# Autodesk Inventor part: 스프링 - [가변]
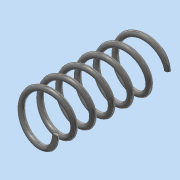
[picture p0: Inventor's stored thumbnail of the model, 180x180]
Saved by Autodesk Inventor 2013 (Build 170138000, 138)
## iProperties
Created: 2016-04
Part Number: 스프링 - [가변]
Material: 강철, 탄소
Document SubType Name: Modeling
Designer: dgall
Density: 7.87 g/cm^3
Mass: 7.38132 g
Surface Area: 18.9918 cm^2
Volume: 0.937905 cm^3
Author: dgall
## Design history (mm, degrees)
sketch "스케치1"
  geometry: L1 (0, 0)-(0, 42); L2 (0, 0)-(8, 0); L3 (0, 42)-(14.42, 42); C1 r 1 at (8, 0)
  constraints: 6 end point, 1 centre point, 1 coincident, 1 parallel, 1 perpendicular, 1 vertical
  dimensions: "d0" = 42 distance of L1.start L1.end (derived); "d1" = 16 diameter of L2.end L1; "d2" = 2 diameter of C1
feature "코일1" pitch "d3" = 10; turns "d5" = 6; dims "d4" = 42 (= d0), "d6" = 0, angle "d7" = 90 deg, angle "d8" = 90 deg, "d9" = 0, "d10" = 0
feature "분할1"
node "작업 평면1"
feature "분할2"
node "솔리드1"
other parameters: "d11" = 0
